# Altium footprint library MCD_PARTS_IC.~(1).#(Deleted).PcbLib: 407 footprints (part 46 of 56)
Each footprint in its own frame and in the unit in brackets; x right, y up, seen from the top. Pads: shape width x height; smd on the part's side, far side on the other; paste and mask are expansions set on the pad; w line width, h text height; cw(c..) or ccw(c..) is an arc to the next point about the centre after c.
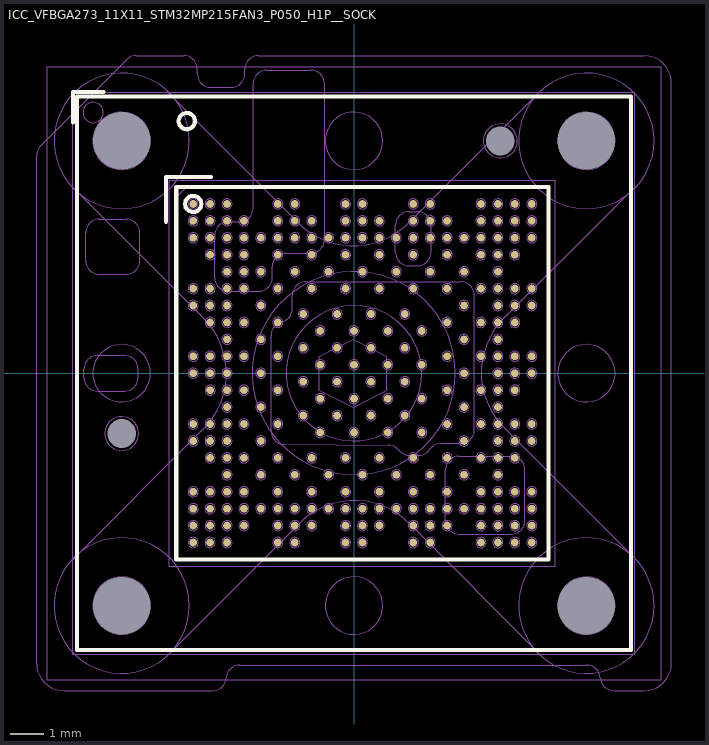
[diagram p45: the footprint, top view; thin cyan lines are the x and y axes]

## ICC_VFBGA273_11X11_STM32MP215FAN3_P050_H1P__SOCKET_IRONWOOD_CS2434374MF [mm]
height 1.2
pads (279):
  round 0.23 smd paste+0.025 mask+0.05: 1A1(-1.5,1.75) 1A3(-0.5,1.75) 1A5(0.5,1.75) 1A7(1.5,1.75) 1B2(-1,1.25) 1B4(0,1.25) 1B6(1,1.25) 1B8(2,1.25) 1C1(-1.5,0.75) 1C3(-0.5,0.75) 1C5(0.5,0.75) 1C7(1.5,0.75) 1D2(-1,0.25) 1D4(0,0.25) 1D6(1,0.25) 1D8(2,0.25) 1E1(-1.5,-0.25) 1E3(-0.5,-0.25) 1E5(0.5,-0.25) 1E7(1.5,-0.25) 1F2(-1,-0.75) 1F4(0,-0.75) 1F6(1,-0.75) 1F8(2,-0.75) 1G1(-1.5,-1.25) 1G3(-0.5,-1.25) 1G5(0.5,-1.25) 1G7(1.5,-1.25) 1H2(-1,-1.75) 1H4(0,-1.75) 1H6(1,-1.75) 1H8(2,-1.75) A1(-4.75,5) A2(-4.25,5) A3(-3.75,5) A6(-2.25,5) A7(-1.75,5) A10(-0.25,5) A11(0.25,5) A14(1.75,5) A15(2.25,5) A18(3.75,5) A19(4.25,5) A20(4.75,5) A21(5.25,5) AA1(-4.75,-5) AA2(-4.25,-5) AA3(-3.75,-5) AA6(-2.25,-5) AA7(-1.75,-5) AA10(-0.25,-5) AA11(0.25,-5) AA14(1.749,-5) AA15(2.25,-5) AA18(3.749,-5) AA19(4.25,-5) AA20(4.75,-5) AA21(5.25,-5) B1(-4.75,4.5) B2(-4.25,4.5) B3(-3.75,4.5) B4(-3.25,4.5) B6(-2.25,4.5) B7(-1.75,4.5) B8(-1.25,4.5) B10(-0.25,4.5) B11(0.25,4.5) B12(0.75,4.5) B14(1.75,4.5) B15(2.25,4.5) B16(2.75,4.5) B18(3.75,4.5) B19(4.25,4.5) B20(4.75,4.5) B21(5.25,4.5) C1(-4.75,4) C2(-4.25,4) C3(-3.75,4) C4(-3.25,4) C5(-2.75,4) C6(-2.25,4) C7(-1.75,4) C8(-1.25,4) C9(-0.75,4) C10(-0.25,4) C11(0.25,4) C12(0.75,4) C13(1.25,4) C14(1.75,4) C15(2.25,4) C16(2.75,4) C17(3.25,4) C18(3.75,4) C19(4.25,4) C20(4.75,4) C21(5.25,4) D2(-4.25,3.5) D3(-3.75,3.5) D4(-3.25,3.5) D6(-2.25,3.5) D8(-1.25,3.5) D10(-0.25,3.5) D12(0.75,3.5) D14(1.75,3.5) D16(2.75,3.5) D18(3.75,3.5) D19(4.25,3.5) D20(4.75,3.5) E3(-3.75,3) E4(-3.25,3) E5(-2.75,3) E7(-1.75,3) E9(-0.75,3) E11(0.25,3) E13(1.25,3) E15(2.25,3) E17(3.25,3) E19(4.25,3) F1(-4.75,2.5) F2(-4.25,2.5) F3(-3.75,2.5) F4(-3.25,2.5) F6(-2.25,2.5) F8(-1.25,2.5) F10(-0.25,2.5) F12(0.75,2.5) F14(1.75,2.5) F16(2.75,2.5) F18(3.75,2.5) F19(4.25,2.5) F20(4.75,2.5) F21(5.25,2.5) G1(-4.75,2) G2(-4.25,2) G3(-3.75,2) G5(-2.75,2) G17(3.25,2) G19(4.25,2) G20(4.75,2) G21(5.25,2) H2(-4.25,1.5) H3(-3.75,1.5) H4(-3.25,1.5) H6(-2.25,1.5) H16(2.75,1.5) H18(3.75,1.5) H19(4.25,1.5) H20(4.75,1.5) J3(-3.75,1) J5(-2.75,1) J17(3.25,1) J19(4.25,1) K1(-4.75,0.5) K2(-4.25,0.5) K3(-3.75,0.5) K4(-3.25,0.5) K6(-2.25,0.5) K16(2.749,0.5) K18(3.749,0.5) K19(4.25,0.5) K20(4.75,0.5) K21(5.25,0.5) L1(-4.75,0) L2(-4.25,0) L3(-3.75,0) L5(-2.75,0) L17(3.25,0) L19(4.25,0) L20(4.75,0) L21(5.249,0) M2(-4.25,-0.5) M3(-3.75,-0.5) M4(-3.25,-0.5) M6(-2.25,-0.5) M16(2.75,-0.5) M18(3.75,-0.5) M19(4.25,-0.5) M20(4.75,-0.5) N3(-3.75,-1) N5(-2.75,-1) N17(3.25,-1) N19(4.25,-1) P1(-4.75,-1.5) P2(-4.25,-1.5) P3(-3.75,-1.5) P4(-3.25,-1.5) P6(-2.25,-1.5) P16(2.75,-1.5) P18(3.75,-1.5) P19(4.25,-1.5) P20(4.75,-1.5) P21(5.25,-1.5) R1(-4.75,-2) R2(-4.25,-2) R3(-3.75,-2) R5(-2.75,-2) R17(3.25,-2) R19(4.25,-2) R20(4.75,-2) R21(5.25,-2) T2(-4.25,-2.5) T3(-3.75,-2.5) T4(-3.25,-2.5) T6(-2.25,-2.5) T8(-1.25,-2.5) T10(-0.25,-2.5) T12(0.75,-2.5) T14(1.75,-2.5) T16(2.75,-2.5) T18(3.749,-2.5) T19(4.25,-2.5) T20(4.75,-2.5) U3(-3.75,-3) U5(-2.75,-3) U7(-1.75,-3) U9(-0.75,-3) U11(0.25,-3) U13(1.25,-3) U15(2.25,-3) U17(3.25,-3) U19(4.25,-3) V1(-4.75,-3.5) V2(-4.25,-3.5) V3(-3.75,-3.5) V4(-3.25,-3.5) V6(-2.25,-3.5) V8(-1.25,-3.5) V10(-0.251,-3.5) V12(0.749,-3.5) V14(1.75,-3.5) V16(2.75,-3.5) V18(3.75,-3.5) V19(4.25,-3.5) V20(4.75,-3.5) V21(5.25,-3.5) W1(-4.75,-4) W2(-4.25,-4) W3(-3.75,-4) W4(-3.25,-4) W5(-2.75,-4) W6(-2.25,-4) W7(-1.75,-4) W8(-1.25,-4) W9(-0.75,-4) W10(-0.25,-4) W11(0.25,-4) W12(0.75,-4) W13(1.25,-4) W14(1.75,-4) W15(2.25,-4) W16(2.75,-4) W17(3.25,-4) W18(3.749,-4) W19(4.25,-4) W20(4.75,-4) W21(5.25,-4) Y1(-4.75,-4.5) Y2(-4.25,-4.5) Y3(-3.75,-4.5) Y4(-3.25,-4.5) Y6(-2.25,-4.5) Y7(-1.75,-4.5) Y8(-1.25,-4.5) Y10(-0.25,-4.5) Y11(0.25,-4.5) Y12(0.75,-4.5) Y14(1.75,-4.5) Y15(2.25,-4.5) Y16(2.75,-4.5) Y18(3.749,-4.5) Y19(4.25,-4.5) Y20(4.75,-4.5) Y21(5.25,-4.5)
  round 0 hole 0.85 unplated mask+0.05: NPTH1(4.323,6.863) NPTH2(-6.862,-1.782)
  round 0 hole 1.7 unplated mask+0.05: PTH1(-6.862,6.863) PTH2(6.863,6.863) PTH3(6.863,-6.862) PTH4(-6.862,-6.862)
Top Layer:
  lines w0.1: 4.75,2.5 ccw(c4.75,2.5) 4.75,2.5
Top Overlay:
  circle w0.12: c-4.939,7.446 r0.24
  circle w0.12: c-4.75,5 r0.24
  lines w0.12: -8.302,7.402 -8.302,8.302 -7.402,8.302 ; -5.55,4.475 -5.55,5.8 -4.225,5.8 ; -8.175,-8.175 -8.175,8.175 8.175,8.175 8.175,-8.175 -8.175,-8.175 ; -5.25,-5.5 -5.25,5.5 5.75,5.5 5.75,-5.5 -5.25,-5.5
M8-Bottom Info:
  circle w0.01: c-0.002,0.002 r2
  circle w0.01: c-6.862,6.863 r2
  circle w0.01: c6.863,6.863 r2
  circle w0.01: c6.863,-6.862 r2
  circle w0.01: c-6.862,-6.862 r2
  lines w0.01: -8.327,-5.523 -4.475,-1.671 ; -8.327,5.502 -4.502,1.677 cw(c-6.065,-0.01) -4.474,-1.671 ; -5.527,8.327 -1.675,4.475 ; -5.502,-8.323 -1.677,-4.498 cw(c0.01,-6.06) 1.671,-4.47 ; -1.676,4.474 ccw(c-0.015,6.065) 1.673,4.502 5.498,8.327 ; 1.671,-4.47 5.523,-8.323 ; 4.47,1.676 ccw(c6.06,0.015) 4.498,-1.673 8.323,-5.498 ; 4.47,1.675 8.323,5.527
  text "Max Height :" at -3.652,2.477 h1.52
  text "1.5mm" at -2.102,-3.248 h1.52
M14-Top Assembly:
  drawing of 295 lines, arcs and shapes, not listed
  text "'.Designator'" at 0.248,0.002 h0.75
  text "A1" at -5,4.8 h0.4
M15-Bottom Assembly:
  circle w0.01: c6.863,6.863 r0.85
  circle w0.01: c6.863,-6.863 r0.85
  circle w0.01: c-6.863,-6.863 r0.85
  circle w0.01: c-6.863,6.863 r0.85
  circle w0.01: c-6.863,-1.783 r0.5
  circle w0.01: c4.323,6.863 r0.5
  lines w0.01: -9.375,-8.575 ccw(c-8.575,-8.575) -8.575,-9.375 -4.174,-9.375 ccw(c-4.174,-8.975) -3.774,-8.997 cw(c-3.375,-9.02) -3.375,-8.62 6.875,-8.62 cw(c6.875,-9.02) 7.274,-8.997 ccw(c7.674,-8.975) 7.674,-9.375 8.575,-9.375 ccw(c8.575,-8.575) 9.375,-8.575 9.375,8.575 ccw(c8.575,8.575) 8.575,9.375 -2.825,9.375 ccw(c-2.825,8.975) -3.225,8.975 -3.225,8.845 cw(c-3.625,8.845) -3.625,8.445 -4.225,8.445 cw(c-4.225,8.845) -4.625,8.845 -4.625,8.975 ccw(c-5.025,8.975) -5.025,9.375 -6.434,9.375 ccw(c-6.434,8.975) -6.717,9.258 -9.258,6.717 ccw(c-8.975,6.434) -9.375,6.434 -9.375,-8.575 ; -7.975,-0.125 ccw(c-7.575,-0.125) -7.575,-0.525 -6.775,-0.525 ccw(c-6.775,-0.125) -6.375,-0.125 -6.375,0.125 ccw(c-6.775,0.125) -6.775,0.525 -7.575,0.525 ccw(c-7.575,0.125) -7.975,0.125 -7.975,-0.125 ; -7.925,3.325 ccw(c-7.525,3.325) -7.525,2.925 -6.725,2.925 ccw(c-6.725,3.325) -6.325,3.325 -6.325,4.15 ccw(c-6.725,4.15) -6.725,4.55 -7.525,4.55 ccw(c-7.525,4.15) -7.925,4.15 -7.925,3.325 ; -4.115,2.82 ccw(c-3.715,2.82) -3.715,2.42 -2.815,2.42 ccw(c-2.815,2.82) -2.415,2.82 -2.415,3.15 cw(c-2.015,3.15) -2.015,3.55 -1.27,3.55 ccw(c-1.27,3.95) -0.87,3.95 -0.87,8.55 ccw(c-1.27,8.55) -1.27,8.95 -2.58,8.95 ccw(c-2.58,8.55) -2.98,8.55 -2.98,4.877 cw(c-3.38,4.877) -3.38,4.477 -3.715,4.477 ccw(c-3.715,4.077) -4.115,4.077 -4.115,2.82 ; -2.45,-1.7 ccw(c-2.05,-1.7) -2.053,-2.1 1.013,-2.121 cw(c1.01,-2.521) 1.324,-2.273 ccw(c1.638,-2.025) 1.638,-2.425 1.903,-2.425 ccw(c1.903,-2.025) 2.234,-2.25 cw(c2.565,-2.475) 2.565,-2.075 3.15,-2.075 ccw(c3.15,-1.675) 3.55,-1.675 3.55,2.3 ccw(c3.15,2.3) 3.15,2.7 -1.425,2.7 ccw(c-1.425,2.3) -1.825,2.3 -1.825,1.906 cw(c-2.225,1.906) -2.138,1.516 ccw(c-2.05,1.125) -2.45,1.125 -2.45,-1.7 ; 1.225,3.575 ccw(c1.625,3.575) 1.625,3.175 1.875,3.175 ccw(c1.875,3.575) 2.275,3.575 2.275,4.375 ccw(c1.875,4.375) 1.875,4.775 1.625,4.775 ccw(c1.625,4.375) 1.225,4.375 1.225,3.575 ; 2.7,-4.35 ccw(c3.1,-4.35) 3.1,-4.75 4.65,-4.75 ccw(c4.65,-4.35) 5.05,-4.35 5.05,-2.85 ccw(c4.65,-2.85) 4.65,-2.45 3.1,-2.45 ccw(c3.1,-2.85) 2.7,-2.85 2.7,-4.35
  text "Max Height 1.2mm" at 2.307,-4.361 h1
  text "Max Height 1.2mm" at -8.175,-2.483 h1
  text "Max Height 1.2mm" at -8.302,-0.763 h1
  text "Max Height 1.2mm" at -8.302,2.922 h1
  text "Max Height 1.2mm" at 5.235,5.7 h1
  text "Max Height 1.2mm" at 0.28,3.147 h1
  text "Max Height 1.2mm" at -1.027,-0.404 h1
  text "Max Height 1.2mm" at -1.112,4.442 h1
M16-Top Courtyard:
  lines w0.01: -8.302,-8.298 8.298,-8.298 8.298,8.302 -8.302,8.302 -8.302,-8.298 ; -5.45,-5.7 5.95,-5.7 5.95,5.7 -5.45,5.7 -5.45,-5.7
M17-Bottom Courtyard:
  lines w0.01: -9.052,-9.048 -9.052,9.052 9.073,9.052 9.073,-9.048 -9.052,-9.048
3D body: height 3.7, standoff 0, extent -8.862,6.863 -4.862,8.863
3D body: height 3.7, standoff 0, extent -8.862,4.862 -4.862,6.863
3D body: height 3.7, standoff 0, extent 4.862,4.862 8.863,6.863
3D body: height 3.7, standoff 0, extent 4.862,6.863 8.863,8.863
3D body: height 3.7, standoff 0, extent 4.862,-8.862 8.863,-6.862
3D body: height 3.7, standoff 0, extent 4.862,-6.862 8.863,-4.862
3D body: height 3.7, standoff 0, extent -8.862,-8.862 -4.862,-6.862
3D body: height 3.7, standoff 0, extent -8.862,-6.862 -4.862,-4.862
3D body: height 3.7, standoff 1.2, extent -8.502,-8.623 8.863,8.416
3D body: height 6, standoff 5, extent -7.706,-0.846 -6.012,0.851
3D body: height 6, standoff 5, extent -0.846,6.014 0.848,7.711
3D body: height 6, standoff 5, extent 6.019,-0.846 7.713,0.851
3D body: height 6, standoff 5, extent -0.846,-7.711 0.848,-6.014
3D body: height 8.25, standoff 5, extent -3.002,-2.997 2.998,3.002
3D body: height 5, standoff 0, extent -8.115,-8.11 8.11,8.115
3D body: height 8.26, standoff 8.25, extent -1.002,-0.998 0.998,1.002
3D body: height 0.36, standoff -0.04, extent 1.801,-1.947 2.2,-1.553
3D body: height 0.36, standoff -0.04, extent 0.801,-1.947 1.2,-1.553
3D body: height 0.36, standoff -0.04, extent -0.199,-1.947 0.2,-1.553
3D body: height 0.36, standoff -0.04, extent -1.199,-1.947 -0.8,-1.553
3D body: height 0.36, standoff -0.04, extent 1.301,-1.447 1.7,-1.053
3D body: height 0.36, standoff -0.04, extent 0.301,-1.447 0.7,-1.053
3D body: height 0.36, standoff -0.04, extent -0.699,-1.447 -0.3,-1.053
3D body: height 0.36, standoff -0.04, extent -1.699,-1.447 -1.3,-1.053
3D body: height 0.36, standoff -0.04, extent 1.801,-0.947 2.2,-0.553
3D body: height 0.36, standoff -0.04, extent 0.801,-0.947 1.2,-0.553
3D body: height 0.36, standoff -0.04, extent -0.199,-0.947 0.2,-0.553
3D body: height 0.36, standoff -0.04, extent -1.199,-0.947 -0.8,-0.553
3D body: height 0.36, standoff -0.04, extent 1.301,-0.447 1.7,-0.053
3D body: height 0.36, standoff -0.04, extent 0.301,-0.447 0.7,-0.053
3D body: height 0.36, standoff -0.04, extent -0.699,-0.447 -0.3,-0.053
3D body: height 0.36, standoff -0.04, extent -1.699,-0.447 -1.3,-0.053
3D body: height 0.36, standoff -0.04, extent 1.801,0.053 2.2,0.447
3D body: height 0.36, standoff -0.04, extent 0.801,0.053 1.2,0.447
3D body: height 0.36, standoff -0.04, extent -0.199,0.053 0.2,0.447
3D body: height 0.36, standoff -0.04, extent -1.199,0.053 -0.8,0.447
3D body: height 0.36, standoff -0.04, extent 1.301,0.553 1.7,0.947
3D body: height 0.36, standoff -0.04, extent 0.301,0.553 0.7,0.947
3D body: height 0.36, standoff -0.04, extent -0.699,0.553 -0.3,0.947
3D body: height 0.36, standoff -0.04, extent -1.699,0.553 -1.3,0.947
3D body: height 0.36, standoff -0.04, extent -1.199,1.053 -0.8,1.447
3D body: height 0.36, standoff -0.04, extent -0.199,1.053 0.2,1.447
3D body: height 0.36, standoff -0.04, extent 0.801,1.053 1.2,1.447
3D body: height 0.36, standoff -0.04, extent 1.801,1.053 2.2,1.447
3D body: height 0.36, standoff -0.04, extent 1.301,1.553 1.7,1.947
3D body: height 0.36, standoff -0.04, extent 0.301,1.553 0.7,1.947
3D body: height 0.36, standoff -0.04, extent -0.699,1.553 -0.3,1.947
3D body: height 0.36, standoff -0.04, extent -1.699,1.553 -1.3,1.947
3D body: height 0.36, standoff -0.04, extent -0.449,2.303 -0.05,2.697
3D body: height 0.36, standoff -0.04, extent -0.45,-2.7 -0.05,-2.3
3D body: height 1.01, standoff 1, extent -5.05,4.7 -4.45,5.3
3D body: height 0.36, standoff -0.04, extent 4.55,-5.197 4.949,-4.803
3D body: height 0.36, standoff -0.04, extent 5.05,-4.697 5.449,-4.303
3D body: height 0.36, standoff -0.04, extent 4.05,-5.197 4.449,-4.803
3D body: height 0.36, standoff -0.04, extent 1.551,-4.697 1.95,-4.303
3D body: height 0.36, standoff -0.04, extent 2.55,-4.697 2.949,-4.303
3D body: height 0.36, standoff -0.04, extent -3.949,-5.197 -3.55,-4.803
3D body: height 0.36, standoff -0.04, extent -3.949,-4.697 -3.55,-4.303
3D body: height 0.36, standoff -0.04, extent -1.949,-4.697 -1.55,-4.303
3D body: height 0.36, standoff -0.04, extent -1.449,-4.697 -1.05,-4.303
3D body: height 0.36, standoff -0.04, extent -0.449,-5.197 -0.05,-4.803
3D body: height 0.36, standoff -0.04, extent 4.55,-4.697 4.949,-4.303
3D body: height 0.36, standoff -0.04, extent 4.05,-4.697 4.449,-4.303
3D body: height 0.36, standoff -0.04, extent 3.55,-5.197 3.95,-4.803
3D body: height 0.36, standoff -0.04, extent 0.051,-4.697 0.45,-4.303
3D body: height 0.36, standoff -0.04, extent 2.05,-5.197 2.449,-4.803
3D body: height 0.36, standoff -0.04, extent -4.949,-5.197 -4.55,-4.803
3D body: height 0.36, standoff -0.04, extent -4.449,-5.197 -4.05,-4.803
3D body: height 0.36, standoff -0.04, extent -2.449,-5.197 -2.05,-4.803
3D body: height 0.36, standoff -0.04, extent -1.949,-5.197 -1.55,-4.803
3D body: height 0.36, standoff -0.04, extent 5.05,-5.197 5.449,-4.803
3D body: height 0.36, standoff -0.04, extent 3.55,-4.697 3.949,-4.303
3D body: height 0.36, standoff -0.04, extent -0.449,-4.697 -0.05,-4.303
3D body: height 0.36, standoff -0.04, extent 0.55,-4.697 0.95,-4.303
3D body: height 0.36, standoff -0.04, extent 2.05,-4.697 2.45,-4.303
3D body: height 0.36, standoff -0.04, extent -4.949,-4.697 -4.55,-4.303
3D body: height 0.36, standoff -0.04, extent -4.449,-4.697 -4.05,-4.303
3D body: height 0.36, standoff -0.04, extent -3.449,-4.697 -3.05,-4.303
3D body: height 0.36, standoff -0.04, extent -2.449,-4.697 -2.05,-4.303
3D body: height 0.36, standoff -0.04, extent 5.05,-3.697 5.449,-3.303
3D body: height 0.36, standoff -0.04, extent 4.55,-3.697 4.949,-3.303
3D body: height 0.36, standoff -0.04, extent 4.05,-3.697 4.449,-3.303
3D body: height 0.36, standoff -0.04, extent 5.05,-4.197 5.449,-3.803
3D body: height 0.36, standoff -0.04, extent 4.55,-4.197 4.949,-3.803
3D body: height 0.36, standoff -0.04, extent 1.05,-4.197 1.45,-3.803
3D body: height 0.36, standoff -0.04, extent 2.55,-3.697 2.949,-3.303
3D body: height 0.36, standoff -0.04, extent -4.449,-3.697 -4.05,-3.303
3D body: height 0.36, standoff -0.04, extent -3.949,-3.697 -3.55,-3.303
3D body: height 0.36, standoff -0.04, extent -2.949,-4.197 -2.55,-3.803
3D body: height 0.36, standoff -0.04, extent -1.449,-3.697 -1.05,-3.303
3D body: height 0.36, standoff -0.04, extent 4.55,-2.697 4.949,-2.303
3D body: height 0.36, standoff -0.04, extent 4.05,-2.697 4.449,-2.303
3D body: height 0.36, standoff -0.04, extent 4.05,-3.197 4.45,-2.803
3D body: height 0.36, standoff -0.04, extent 3.051,-3.197 3.45,-2.803
3D body: height 0.36, standoff -0.04, extent -0.949,-3.197 -0.55,-2.803
3D body: height 0.36, standoff -0.04, extent 1.051,-3.197 1.45,-2.803
3D body: height 0.36, standoff -0.04, extent 2.05,-3.197 2.45,-2.803
3D body: height 0.36, standoff -0.04, extent -3.949,-3.197 -3.55,-2.803
3D body: height 0.36, standoff -0.04, extent -2.949,-3.197 -2.55,-2.803
3D body: height 0.36, standoff -0.04, extent -1.949,-3.197 -1.55,-2.803
3D body: height 0.36, standoff -0.04, extent 5.05,-2.197 5.449,-1.803
3D body: height 0.36, standoff -0.04, extent 4.55,-2.197 4.949,-1.803
3D body: height 0.36, standoff -0.04, extent 4.05,-2.197 4.449,-1.803
3D body: height 0.36, standoff -0.04, extent 3.05,-2.197 3.45,-1.803
3D body: height 0.36, standoff -0.04, extent -4.449,-2.197 -4.05,-1.803
3D body: height 0.36, standoff -0.04, extent -3.949,-2.197 -3.55,-1.803
3D body: height 0.36, standoff -0.04, extent -2.949,-2.197 -2.55,-1.803
3D body: height 0.36, standoff -0.04, extent 4.051,-1.197 4.45,-0.803
3D body: height 0.36, standoff -0.04, extent 4.551,-1.697 4.95,-1.303
3D body: height 0.36, standoff -0.04, extent 4.051,-1.697 4.45,-1.303
3D body: height 0.36, standoff -0.04, extent 3.051,-1.197 3.45,-0.803
3D body: height 0.36, standoff -0.04, extent -3.949,-1.197 -3.55,-0.803
3D body: height 0.36, standoff -0.04, extent -2.949,-1.197 -2.55,-0.803
3D body: height 0.36, standoff -0.04, extent 4.551,-0.697 4.95,-0.303
3D body: height 0.36, standoff -0.04, extent 4.051,-0.697 4.45,-0.303
3D body: height 0.36, standoff -0.04, extent -4.449,-0.697 -4.05,-0.303
3D body: height 0.36, standoff -0.04, extent -3.949,-0.697 -3.55,-0.303
3D body: height 0.36, standoff -0.04, extent 4.55,-0.197 4.949,0.197
3D body: height 0.36, standoff -0.04, extent 4.05,-0.197 4.45,0.197
3D body: height 0.36, standoff -0.04, extent 4.55,0.303 4.949,0.697
3D body: height 0.36, standoff -0.04, extent 4.05,0.303 4.45,0.697
3D body: height 0.36, standoff -0.04, extent -4.949,0.303 -4.55,0.697
3D body: height 0.36, standoff -0.04, extent -4.449,0.303 -4.05,0.697
3D body: height 0.36, standoff -0.04, extent -3.949,0.303 -3.55,0.697
3D body: height 0.36, standoff -0.04, extent 5.05,0.303 5.449,0.697
3D body: height 0.36, standoff -0.04, extent 4.05,0.803 4.45,1.197
3D body: height 0.36, standoff -0.04, extent 3.051,0.803 3.45,1.197
3D body: height 0.36, standoff -0.04, extent -3.949,0.803 -3.55,1.197
3D body: height 0.36, standoff -0.04, extent -2.949,0.803 -2.55,1.197
3D body: height 0.36, standoff -0.04, extent 4.551,1.303 4.95,1.697
3D body: height 0.36, standoff -0.04, extent 5.051,1.803 5.45,2.197
3D body: height 0.36, standoff -0.04, extent 4.551,1.803 4.95,2.197
3D body: height 0.36, standoff -0.04, extent 4.051,1.803 4.45,2.197
3D body: height 0.36, standoff -0.04, extent 3.051,1.803 3.45,2.197
3D body: height 0.36, standoff -0.04, extent -4.949,1.803 -4.55,2.197
3D body: height 0.36, standoff -0.04, extent -4.449,1.803 -4.05,2.197
3D body: height 0.36, standoff -0.04, extent -3.949,1.803 -3.55,2.197
3D body: height 0.36, standoff -0.04, extent -2.949,1.803 -2.55,2.197
3D body: height 0.36, standoff -0.04, extent 5.051,2.303 5.45,2.697
3D body: height 0.36, standoff -0.04, extent 3.051,2.803 3.45,3.197
3D body: height 0.36, standoff -0.04, extent 2.051,2.803 2.45,3.197
3D body: height 0.36, standoff -0.04, extent -1.949,2.803 -1.55,3.197
3D body: height 0.36, standoff -0.04, extent 0.051,2.803 0.45,3.197
3D body: height 0.36, standoff -0.04, extent 1.051,2.803 1.45,3.197
3D body: height 0.36, standoff -0.04, extent -4.949,2.303 -4.55,2.697
3D body: height 0.36, standoff -0.04, extent -4.449,2.303 -4.05,2.697
3D body: height 0.36, standoff -0.04, extent -3.949,2.303 -3.55,2.697
3D body: height 0.36, standoff -0.04, extent -2.949,2.803 -2.55,3.197
3D body: height 0.36, standoff -0.04, extent 4.051,2.803 4.45,3.197
3D body: height 0.36, standoff -0.04, extent 4.551,3.303 4.95,3.697
3D body: height 0.36, standoff -0.04, extent 4.051,3.303 4.45,3.697
3D body: height 0.36, standoff -0.04, extent -0.949,2.803 -0.55,3.197
3D body: height 0.36, standoff -0.04, extent 1.551,3.303 1.95,3.697
3D body: height 0.36, standoff -0.04, extent 2.551,3.303 2.95,3.697
3D body: height 0.36, standoff -0.04, extent -4.449,3.303 -4.05,3.697
3D body: height 0.36, standoff -0.04, extent -3.949,3.303 -3.55,3.697
3D body: height 0.36, standoff -0.04, extent -2.449,3.303 -2.05,3.697
3D body: height 0.36, standoff -0.04, extent -1.449,3.303 -1.05,3.697
3D body: height 0.36, standoff -0.04, extent 5.051,4.303 5.45,4.697
3D body: height 0.36, standoff -0.04, extent 4.551,4.303 4.95,4.697
3D body: height 0.36, standoff -0.04, extent 4.051,4.303 4.45,4.697
3D body: height 0.36, standoff -0.04, extent 3.551,4.303 3.95,4.697
3D body: height 0.36, standoff -0.04, extent -2.449,4.303 -2.05,4.697
3D body: height 0.36, standoff -0.04, extent -0.449,4.803 -0.05,5.197
3D body: height 0.36, standoff -0.04, extent 1.551,4.303 1.95,4.697
3D body: height 0.36, standoff -0.04, extent 2.051,4.303 2.45,4.697
3D body: height 0.36, standoff -0.04, extent 2.551,4.303 2.95,4.697
3D body: height 0.36, standoff -0.04, extent -4.949,4.303 -4.55,4.697
3D body: height 0.36, standoff -0.04, extent -4.449,4.303 -4.05,4.697
3D body: height 0.36, standoff -0.04, extent -3.949,4.303 -3.55,4.697
3D body: height 0.36, standoff -0.04, extent -3.449,4.303 -3.05,4.697
3D body: height 0.36, standoff -0.04, extent -2.449,4.803 -2.05,5.197
3D body: height 0.36, standoff -0.04, extent -3.949,4.803 -3.55,5.197
3D body: height 0.36, standoff -0.04, extent -4.449,4.803 -4.05,5.197
3D body: height 0.36, standoff -0.04, extent -4.949,4.803 -4.55,5.197
3D body: height 0.36, standoff -0.04, extent 2.051,4.803 2.45,5.197
3D body: height 0.36, standoff -0.04, extent -1.949,4.803 -1.55,5.197
3D body: height 0.36, standoff -0.04, extent 3.551,4.803 3.95,5.197
3D body: height 0.36, standoff -0.04, extent 4.051,4.803 4.45,5.197
3D body: height 0.36, standoff -0.04, extent 4.551,4.803 4.95,5.197
3D body: height 1, standoff 0.3, extent -5.25,-5.524 5.75,5.524
3D body: height 0.36, standoff -0.04, extent 5.051,4.803 5.45,5.197
3D body: height 0.36, standoff -0.04, extent 0.551,4.303 0.95,4.697
3D body: height 0.36, standoff -0.04, extent 0.051,4.303 0.45,4.697
3D body: height 0.36, standoff -0.04, extent -0.449,4.303 -0.05,4.697
3D body: height 0.36, standoff -0.04, extent -1.449,4.303 -1.05,4.697
3D body: height 0.36, standoff -0.04, extent -1.949,4.303 -1.55,4.697
3D body: height 0.36, standoff -0.04, extent -4.949,3.803 -4.55,4.197
3D body: height 0.36, standoff -0.04, extent -4.449,3.803 -4.05,4.197
3D body: height 0.36, standoff -0.04, extent -3.949,3.803 -3.55,4.197
3D body: height 0.36, standoff -0.04, extent -3.449,3.803 -3.05,4.197
3D body: height 0.36, standoff -0.04, extent -2.949,3.803 -2.55,4.197
3D body: height 0.36, standoff -0.04, extent -2.449,3.803 -2.05,4.197
3D body: height 0.36, standoff -0.04, extent -1.949,3.803 -1.55,4.197
3D body: height 0.36, standoff -0.04, extent -1.449,3.803 -1.05,4.197
3D body: height 0.36, standoff -0.04, extent -0.949,3.803 -0.55,4.197
3D body: height 0.36, standoff -0.04, extent -0.449,3.803 -0.05,4.197
3D body: height 0.36, standoff -0.04, extent 0.051,3.803 0.45,4.197
3D body: height 0.36, standoff -0.04, extent 0.551,3.803 0.95,4.197
3D body: height 0.36, standoff -0.04, extent 1.051,3.803 1.45,4.197
3D body: height 0.36, standoff -0.04, extent 1.551,3.803 1.95,4.197
3D body: height 0.36, standoff -0.04, extent 2.051,3.803 2.45,4.197
3D body: height 0.36, standoff -0.04, extent 2.551,3.803 2.95,4.197
3D body: height 0.36, standoff -0.04, extent 3.051,3.803 3.45,4.197
3D body: height 0.36, standoff -0.04, extent 3.551,3.803 3.95,4.197
3D body: height 0.36, standoff -0.04, extent 4.051,3.803 4.45,4.197
3D body: height 0.36, standoff -0.04, extent 4.551,3.803 4.95,4.197
3D body: height 0.36, standoff -0.04, extent 5.051,3.803 5.45,4.197
3D body: height 0.36, standoff -0.04, extent -3.949,2.803 -3.55,3.197
3D body: height 0.36, standoff -0.04, extent 4.551,2.303 4.95,2.697
3D body: height 0.36, standoff -0.04, extent 4.051,2.303 4.45,2.697
3D body: height 0.36, standoff -0.04, extent 3.551,2.303 3.95,2.697
3D body: height 0.36, standoff -0.04, extent -3.449,2.303 -3.05,2.697
3D body: height 0.36, standoff -0.04, extent 4.051,1.303 4.45,1.697
3D body: height 0.36, standoff -0.04, extent 3.551,1.303 3.95,1.697
3D body: height 0.36, standoff -0.04, extent -3.449,1.303 -3.05,1.697
3D body: height 0.36, standoff -0.04, extent -3.949,1.303 -3.55,1.697
3D body: height 0.36, standoff -0.04, extent -4.449,1.303 -4.05,1.697
3D body: height 0.36, standoff -0.04, extent 3.05,-0.197 3.45,0.197
3D body: height 0.36, standoff -0.04, extent -4.449,-0.197 -4.05,0.197
3D body: height 0.36, standoff -0.04, extent -3.949,-0.197 -3.55,0.197
3D body: height 0.36, standoff -0.04, extent -2.949,-0.197 -2.55,0.197
3D body: height 0.36, standoff -0.04, extent -4.449,-1.697 -4.05,-1.303
3D body: height 0.36, standoff -0.04, extent -3.949,-1.697 -3.55,-1.303
3D body: height 0.36, standoff -0.04, extent -3.449,-1.697 -3.05,-1.303
3D body: height 0.36, standoff -0.04, extent 3.551,-1.697 3.95,-1.303
3D body: height 0.36, standoff -0.04, extent 3.55,-2.697 3.949,-2.303
3D body: height 0.36, standoff -0.04, extent 0.051,-3.197 0.45,-2.803
3D body: height 0.36, standoff -0.04, extent -4.949,-2.197 -4.55,-1.803
3D body: height 0.36, standoff -0.04, extent -4.449,-2.697 -4.05,-2.303
3D body: height 0.36, standoff -0.04, extent -3.949,-2.697 -3.55,-2.303
3D body: height 0.36, standoff -0.04, extent -3.449,-2.697 -3.05,-2.303
3D body: height 0.36, standoff -0.04, extent 4.05,-4.197 4.45,-3.803
3D body: height 0.36, standoff -0.04, extent 3.55,-4.197 3.95,-3.803
3D body: height 0.36, standoff -0.04, extent 3.05,-4.197 3.45,-3.803
3D body: height 0.36, standoff -0.04, extent 2.55,-4.197 2.95,-3.803
3D body: height 0.36, standoff -0.04, extent 2.05,-4.197 2.45,-3.803
3D body: height 0.36, standoff -0.04, extent 1.55,-3.697 1.95,-3.303
3D body: height 0.36, standoff -0.04, extent 1.551,-4.197 1.95,-3.803
3D body: height 0.36, standoff -0.04, extent 0.551,-4.197 0.95,-3.803
3D body: height 0.36, standoff -0.04, extent 0.051,-4.197 0.45,-3.803
3D body: height 0.36, standoff -0.04, extent -0.449,-4.197 -0.05,-3.803
3D body: height 0.36, standoff -0.04, extent -0.949,-4.197 -0.55,-3.803
3D body: height 0.36, standoff -0.04, extent -1.449,-4.197 -1.05,-3.803
3D body: height 0.36, standoff -0.04, extent -1.949,-4.197 -1.55,-3.803
3D body: height 0.36, standoff -0.04, extent -2.449,-3.697 -2.05,-3.303
3D body: height 0.36, standoff -0.04, extent -2.449,-4.197 -2.05,-3.803
3D body: height 0.36, standoff -0.04, extent -3.449,-4.197 -3.05,-3.803
3D body: height 0.36, standoff -0.04, extent -4.949,-3.697 -4.55,-3.303
3D body: height 0.36, standoff -0.04, extent -4.949,-4.197 -4.55,-3.803
3D body: height 0.36, standoff -0.04, extent -4.449,-4.197 -4.05,-3.803
3D body: height 0.36, standoff -0.04, extent -3.949,-4.197 -3.55,-3.803
3D body: height 0.36, standoff -0.04, extent 0.05,4.8 0.45,5.2
3D body: height 0.36, standoff -0.04, extent 1.55,4.8 1.95,5.2
3D body: height 0.36, standoff -0.04, extent -3.449,3.303 -3.05,3.697
3D body: height 0.36, standoff -0.04, extent -0.45,3.3 -0.05,3.7
3D body: height 0.36, standoff -0.04, extent 0.55,3.3 0.95,3.7
3D body: height 0.36, standoff -0.04, extent 3.55,3.3 3.95,3.7
3D body: height 0.36, standoff -0.04, extent -3.449,2.803 -3.05,3.197
3D body: height 0.36, standoff -0.04, extent -2.449,2.303 -2.05,2.697
3D body: height 0.36, standoff -0.04, extent -1.449,2.303 -1.05,2.697
3D body: height 0.36, standoff -0.04, extent 0.551,2.303 0.95,2.697
3D body: height 0.36, standoff -0.04, extent 1.551,2.303 1.95,2.697
3D body: height 0.36, standoff -0.04, extent 2.551,2.303 2.95,2.697
3D body: height 0.36, standoff -0.04, extent -2.449,1.303 -2.05,1.697
3D body: height 0.36, standoff -0.04, extent 2.55,1.3 2.95,1.7
3D body: height 0.36, standoff -0.04, extent -3.45,0.3 -3.05,0.7
3D body: height 0.36, standoff -0.04, extent -2.45,0.3 -2.05,0.7
3D body: height 0.36, standoff -0.04, extent 3.549,0.3 3.949,0.7
3D body: height 0.36, standoff -0.04, extent 2.549,0.3 2.949,0.7
3D body: height 0.36, standoff -0.04, extent -4.95,-0.2 -4.55,0.2
3D body: height 0.36, standoff -0.04, extent 5.049,-0.2 5.449,0.2
3D body: height 0.36, standoff -0.04, extent -3.45,-0.7 -3.05,-0.3
3D body: height 0.36, standoff -0.04, extent -2.45,-0.7 -2.05,-0.3
3D body: height 0.36, standoff -0.04, extent 3.55,-0.7 3.95,-0.3
3D body: height 0.36, standoff -0.04, extent 2.55,-0.7 2.95,-0.3
3D body: height 0.36, standoff -0.04, extent -4.95,-1.7 -4.55,-1.3
3D body: height 0.36, standoff -0.04, extent -2.45,-1.7 -2.05,-1.3
3D body: height 0.36, standoff -0.04, extent 5.05,-1.7 5.45,-1.3
3D body: height 0.36, standoff -0.04, extent 2.55,-1.7 2.95,-1.3
3D body: height 0.36, standoff -0.04, extent -2.449,-2.697 -2.05,-2.303
3D body: height 0.36, standoff -0.04, extent -1.449,-2.697 -1.05,-2.303
3D body: height 0.36, standoff -0.04, extent -0.449,-2.697 -0.05,-2.303
3D body: height 0.36, standoff -0.04, extent 0.551,-2.697 0.95,-2.303
3D body: height 0.36, standoff -0.04, extent 1.551,-2.697 1.95,-2.303
3D body: height 0.36, standoff -0.04, extent 2.551,-2.697 2.95,-2.303
3D body: height 0.36, standoff -0.04, extent -3.449,-3.697 -3.05,-3.303
3D body: height 0.36, standoff -0.04, extent -0.451,-3.7 -0.051,-3.3
3D body: height 0.36, standoff -0.04, extent 0.55,-3.7 0.95,-3.3
3D body: height 0.36, standoff -0.04, extent 3.55,-3.7 3.95,-3.3
3D body: height 0.36, standoff -0.04, extent 0.05,-5.2 0.45,-4.8
3D body: height 0.36, standoff -0.04, extent 1.549,-5.2 1.949,-4.8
